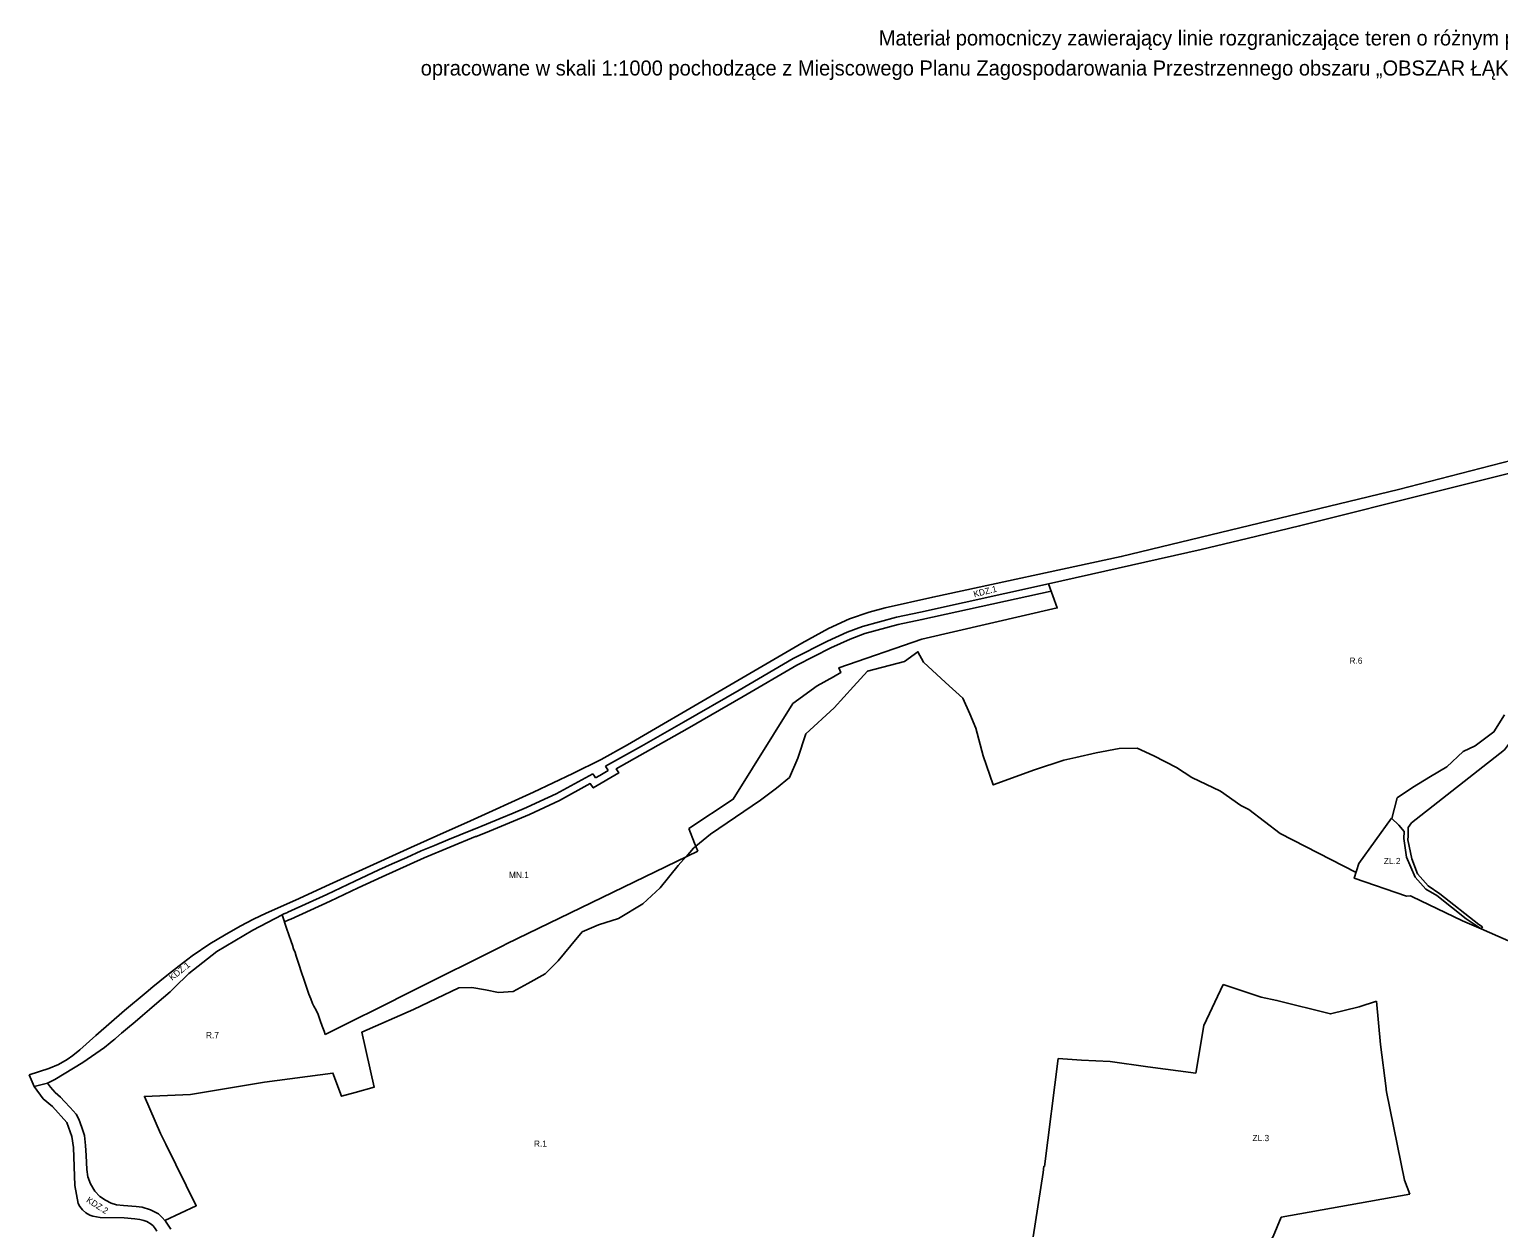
# Model space of a CAD drawing. Extents: x 7418237 to 7420198, y 5543414 to 5545133.
# Drawn here: x 7418237 to 7419412, y 5544174 to 5545133 of the extents above; entities that cross this region are included whole.
import ezdxf

# ---------------------------------------------------------------- set-up
doc = ezdxf.new("R2010")
doc.units = 0
for name, color, linetype in [('info', 7, 'Continuous'), ('linie rozgraniczające', 7, 'Continuous'), ('nieprzekraczalne linie zabudowy', 7, 'Continuous'), ('przeznaczenia terenów', 7, 'Continuous')]:
    doc.layers.add(name, color=color, linetype=linetype)

msp = doc.modelspace()

# ---------------------------------------------------------------- linework, layer by layer
at = {"layer": 'linie rozgraniczające'}
for p, q in [((7418699.9, 5544540.4), (7418697.8, 5544543.7)), ((7418589.7, 5544499.9), (7418562.9, 5544488)), ((7419336, 5544485.9), (7419336.1, 5544491.6)), ((7419362.2, 5544440.2), (7419353.5, 5544445.4)), ((7418449.9, 5544436.7), (7418426.4, 5544426.1)), ((7419338, 5544439.7), (7419341.3, 5544440.1)), ((7419341.3, 5544440.1), (7419342.3, 5544439.6)), ((7419342.3, 5544439.6), (7419382.9, 5544420.2)), ((7419382.9, 5544420.2), (7419397.8, 5544413.7)), ((7418405.6, 5544415.7), (7418393.1, 5544408.7)), ((7418542.9, 5544363.8), (7418615.6, 5544400.2)), ((7418347, 5544376.4), (7418335.9, 5544367.4)), ((7418517, 5544350.8), (7418542.9, 5544363.8)), ((7418542.9, 5544363.8), (7418542.9, 5544363.8)), ((7419191.5, 5544369.2), (7419176, 5544336.3)), ((7419221.8, 5544359.1), (7419191.5, 5544369.2)), ((7418494.3, 5544339.5), (7418517, 5544350.8)), ((7419314, 5544355.9), (7419300.3, 5544351.3)), ((7418473.6, 5544329.1), (7418494.3, 5544339.5)), ((7419176, 5544336.3), (7419169.7, 5544298.3)), ((7419059.6, 5544310.1), (7419048.8, 5544223.6)), ((7419078.3, 5544308.6), (7419059.6, 5544310.1)), ((7419336.5, 5544212.8), (7419322.2, 5544283.4)), ((7418248.3, 5544277.8), (7418255.6, 5544271.6)), ((7418255.6, 5544271.6), (7418267, 5544258.7)), ((7419048.2, 5544223.9), (7419047.5, 5544218.9)), ((7419048.8, 5544223.6), (7419048.2, 5544223.9)), ((7418273.6, 5544208.4), (7418276.2, 5544194.1)), ((7419047.5, 5544218.9), (7419039.6, 5544167.5)), ((7419340.8, 5544201.6), (7419336.5, 5544212.8)), ((7419237.9, 5544183.2), (7419340.8, 5544201.6)), ((7418276.2, 5544194.1), (7418277.6, 5544191.6))]:
    msp.add_line(p, q, dxfattribs=at)
for points in [[(7418875.3, 5544643.7), (7418890.9, 5544650.9), (7418903.3, 5544655.5), (7418930.4, 5544662.8), (7418949.5, 5544666.9), (7419051.8, 5544689.5), (7419173.9, 5544717.1), (7419210.8, 5544725.8), (7419252.6, 5544735.9), (7419477.9, 5544792.5), (7419492.7, 5544796.3), (7419508.2, 5544800.3), (7419538, 5544807.6), (7419572.4, 5544815.5), (7419587.6, 5544818.4), (7419604.4, 5544821.1), (7419625.7, 5544824.5)], [(7419521.6, 5544813.9), (7419331.6, 5544764.9), (7419110, 5544711.3), (7418959.3, 5544678.9), (7418921.3, 5544670.3), (7418908.6, 5544667), (7418892.9, 5544661.5), (7418876.1, 5544653.8), (7418854.6, 5544642.1), (7418787.6, 5544603), (7418715.2, 5544560.8), (7418694.3, 5544549.2), (7418671.5, 5544537.9), (7418640.2, 5544522.9), (7418589.7, 5544499.9)], [(7418764.3, 5544493.9), (7418799.8, 5544517.3), (7418847.4, 5544593.8), (7418866.9, 5544607.9), (7418880, 5544615.3), (7418885.8, 5544618.6), (7418884.3, 5544622.5), (7418950.6, 5544645.3), (7419058.9, 5544670.3), (7419051.8, 5544689.5)], [(7418697.8, 5544543.7), (7418726.5, 5544559.8), (7418760, 5544578.9), (7418804.7, 5544604.6), (7418847.8, 5544629.8), (7418875.3, 5544643.7)], [(7418770, 5544479.7), (7418781.6, 5544489.4), (7418821.7, 5544516.5), (7418834.3, 5544526.2), (7418844.8, 5544534.6), (7418851.4, 5544550.1), (7418858, 5544569.7), (7418880.4, 5544590.3), (7418895.9, 5544607.5), (7418907.1, 5544619.8), (7418936.7, 5544627.4), (7418947.5, 5544635.2), (7418952, 5544627), (7418969.6, 5544610.7), (7418983.3, 5544598.2), (7418988.9, 5544585.5), (7418993.9, 5544574.2), (7418999.7, 5544552), (7419007.7, 5544528.8), (7419040.8, 5544540.9), (7419064.1, 5544548.6), (7419073.7, 5544550.7), (7419090, 5544554.3), (7419108.5, 5544558), (7419122.7, 5544558.2), (7419136.2, 5544551.9), (7419154.2, 5544542.8), (7419166.6, 5544534.7), (7419189.3, 5544523.8), (7419205.7, 5544512.2), (7419212.1, 5544509.2), (7419237.1, 5544489.8), (7419297.8, 5544458.8)], [(7419326.3, 5544502), (7419330.7, 5544518.3), (7419342.9, 5544526.7), (7419357.4, 5544535.5), (7419370.3, 5544543.1), (7419383.4, 5544555.4), (7419393, 5544559.9), (7419408, 5544571.1), (7419416.3, 5544584.7)], [(7419425.9, 5544569.5), (7419416.3, 5544556.9), (7419342.2, 5544498.4), (7419339.3, 5544494.6), (7419339.3, 5544487.9)], [(7418658.2, 5544521.7), (7418687.5, 5544537.7)], [(7418687.5, 5544537.7), (7418688.8, 5544535.8), (7418689.7, 5544534.4)], [(7418689.7, 5544534.4), (7418693.1, 5544536.4), (7418699.9, 5544540.4)], [(7418613.6, 5544502), (7418623.8, 5544506.2), (7418634.5, 5544510.7), (7418645.4, 5544515.8), (7418658.2, 5544521.7)], [(7418592.3, 5544493.2), (7418602.6, 5544497.5), (7418613.6, 5544502)], [(7419336.1, 5544491.6), (7419332, 5544496.5), (7419326.2, 5544502.1), (7419300, 5544465.9)], [(7418497.4, 5544451.8), (7418507, 5544456.3), (7418516.6, 5544460.8), (7418521.9, 5544463.2), (7418527.3, 5544465.6), (7418538.8, 5544470.8), (7418550.3, 5544476), (7418561.1, 5544480.4), (7418571.8, 5544484.8), (7418591.5, 5544492.9), (7418591.9, 5544493), (7418592.1, 5544493.1), (7418592.3, 5544493.2)], [(7418764.3, 5544493.9), (7418768.9, 5544482.2), (7418771.5, 5544475.9)], [(7418562.9, 5544488), (7418542.1, 5544478.6), (7418500.6, 5544459.8), (7418477.2, 5544449), (7418449.9, 5544436.7)], [(7419353.5, 5544445.4), (7419344.9, 5544455), (7419338.1, 5544471), (7419336, 5544485.9)], [(7419339.3, 5544487.9), (7419339.2, 5544484.9), (7419342.4, 5544469.6), (7419346.9, 5544457.7), (7419355.3, 5544448.1), (7419364.8, 5544441.6), (7419395.8, 5544417.2), (7419398.8, 5544415.3)], [(7418345.4, 5544180.5), (7418370.5, 5544192.2), (7418346.3, 5544241.5), (7418342.1, 5544250), (7418329.1, 5544279.7), (7418365.9, 5544281.2), (7418425.1, 5544291), (7418479.8, 5544298.3), (7418486.8, 5544279.8), (7418497.7, 5544282.9), (7418512.8, 5544287.1), (7418503, 5544331.1), (7418544.2, 5544349.2), (7418562.6, 5544358.1), (7418580.5, 5544366.5), (7418590.9, 5544366.7), (7418601.9, 5544364.8), (7418612.3, 5544362.8), (7418623.9, 5544363.6), (7418635.7, 5544369.9), (7418649.6, 5544377.8), (7418659.8, 5544388), (7418670.1, 5544400.4), (7418679.2, 5544411.2), (7418692, 5544416.9), (7418708.1, 5544422), (7418727.7, 5544433.6), (7418741.3, 5544446.4), (7418755.9, 5544464.3), (7418762.2, 5544471.4)], [(7418615.6, 5544400.2), (7418618.6, 5544401.7), (7418771.5, 5544475.9)], [(7419300, 5544465.9), (7419296.3, 5544454.1), (7419338, 5544439.7)], [(7418439.2, 5544424.9), (7418440.7, 5544425.6), (7418442.2, 5544426.2), (7418442.9, 5544426.6), (7418443.7, 5544426.9), (7418475, 5544441.1), (7418486.2, 5544446.5), (7418497.4, 5544451.8)], [(7419397.8, 5544413.7), (7419385.8, 5544421.6), (7419362.2, 5544440.2)], [(7418439.2, 5544424.9), (7418427.4, 5544418.8), (7418415.7, 5544412.6), (7418401.3, 5544404.1), (7418387, 5544395.6)], [(7418426.4, 5544426.1), (7418416.4, 5544421.3), (7418405.6, 5544415.7)], [(7418473.6, 5544329.1), (7418472.7, 5544331.8), (7418471.3, 5544335.9), (7418469.7, 5544340.5), (7418468.1, 5544345.2), (7418466.4, 5544348.6), (7418464.6, 5544351.9), (7418464.1, 5544352.9), (7418463.6, 5544353.9), (7418462.1, 5544357.6), (7418460.6, 5544361.4), (7418459.5, 5544364.6), (7418458.3, 5544367.8), (7418456.5, 5544373.3), (7418454.7, 5544378.8), (7418452.6, 5544385.3), (7418450.5, 5544391.8), (7418449.5, 5544394.7), (7418448.4, 5544397.6), (7418447.4, 5544400.6), (7418446.4, 5544403.6), (7418442.8, 5544414.2), (7418439.2, 5544424.9)], [(7418393.1, 5544408.7), (7418381.4, 5544401.6), (7418367.2, 5544392)], [(7419398.8, 5544415.3), (7419397.8, 5544413.7), (7419428.8, 5544400.2)], [(7418304.6, 5544324.8), (7418305.4, 5544325.5), (7418306.2, 5544326.2), (7418310.9, 5544330.2), (7418315.6, 5544334.2), (7418321.6, 5544339.3), (7418327.5, 5544344.4), (7418333.3, 5544349.3), (7418339, 5544354.2), (7418344.4, 5544358.7), (7418349.7, 5544363.3), (7418351.3, 5544364.9), (7418352.8, 5544366.5), (7418364.6, 5544377.9), (7418375.8, 5544386.8), (7418387, 5544395.6)], [(7418367.2, 5544392), (7418356.8, 5544384.2), (7418347, 5544376.4)], [(7418335.9, 5544367.4), (7418330.4, 5544362.9), (7418313.3, 5544348.3), (7418290.4, 5544328.3), (7418277.4, 5544316.8), (7418271.9, 5544312.3), (7418267.4, 5544309.1), (7418260.5, 5544305.3), (7418252.7, 5544302.1), (7418237.1, 5544297)], [(7419300.3, 5544351.3), (7419277.2, 5544345.7), (7419234.5, 5544356.4), (7419221.8, 5544359.1)], [(7419321.8, 5544286), (7419317.2, 5544321.1), (7419314, 5544355.9)], [(7418297.2, 5544318.9), (7418279.9, 5544306.7), (7418257.4, 5544293.2), (7418251.6, 5544290.2), (7418241.1, 5544287.7)], [(7418304.6, 5544324.8), (7418301.7, 5544322.5), (7418297.2, 5544318.9)], [(7419169.7, 5544298.3), (7419131.4, 5544303.4), (7419101.3, 5544307.5), (7419078.3, 5544308.6)], [(7418237.1, 5544297), (7418241.1, 5544287.5), (7418248.3, 5544277.8)], [(7418251.6, 5544290.2), (7418253.9, 5544287.1), (7418257.8, 5544282.8), (7418262.1, 5544279.2), (7418265.3, 5544275.7), (7418269.7, 5544270.7), (7418274.5, 5544265.4), (7418276.7, 5544261.4), (7418279.1, 5544254.9), (7418281.1, 5544248.5), (7418282.1, 5544240.5), (7418282.6, 5544232.5), (7418283, 5544221.2), (7418283.9, 5544215.3), (7418285.9, 5544209.7), (7418289.4, 5544204), (7418293.5, 5544199.7), (7418297.9, 5544196.6), (7418302.6, 5544194.4), (7418306.8, 5544193.1), (7418312.4, 5544192.5), (7418322.5, 5544191.7), (7418327.2, 5544191), (7418333.9, 5544189.1), (7418340.4, 5544185.7)], [(7419322.2, 5544283.4), (7419321.9, 5544285.1), (7419321.8, 5544286)], [(7418267, 5544258.7), (7418271.2, 5544247.5), (7418272.3, 5544238.7), (7418273.6, 5544208.4)], [(7418277.6, 5544191.6), (7418279.6, 5544189), (7418282.2, 5544186.6), (7418285.6, 5544184.8), (7418287.8, 5544184), (7418293.7, 5544182.9), (7418313, 5544182.5), (7418321.4, 5544181.7), (7418325.4, 5544181.2), (7418328.6, 5544180.4), (7418331, 5544179.6), (7418334.5, 5544177.6), (7418336, 5544176.1), (7418337.8, 5544174.1), (7418339.1, 5544172)], [(7418350.1, 5544173.4), (7418346, 5544179.8), (7418343.1, 5544183.2), (7418340.4, 5544185.7)], [(7419215.7, 5544151.9), (7419222.8, 5544153.8), (7419231.5, 5544167.6), (7419237.9, 5544183.2)]]:
    msp.add_lwpolyline(points, dxfattribs=at)
at = {"layer": 'nieprzekraczalne linie zabudowy'}
for points in [[(7419053.9, 5544683.8), (7418950.7, 5544661), (7418931.8, 5544657), (7418905.1, 5544649.8), (7418893.2, 5544645.4), (7418877.9, 5544638.3), (7418850.7, 5544624.6), (7418807.7, 5544599.4), (7418762.9, 5544573.7), (7418729.5, 5544554.6), (7418706.3, 5544541.6), (7418708.3, 5544538.4), (7418687.9, 5544526.4), (7418685.5, 5544529.8), (7418660.9, 5544516.4), (7418636.9, 5544505.2), (7418604.9, 5544491.9), (7418595, 5544487.8), (7418594.5, 5544487.6), (7418594, 5544487.4), (7418593.9, 5544487.4), (7418552.7, 5544470.5), (7418519.1, 5544455.3), (7418500, 5544446.4), (7418477.5, 5544435.7), (7418446.2, 5544421.5), (7418444.6, 5544420.8), (7418441.1, 5544419.2)], [(7418762.1, 5544471.3), (7418768.2, 5544478.2), (7418770, 5544479.7)]]:
    msp.add_lwpolyline(points, dxfattribs=at)

# ---------------------------------------------------------------- texts
at = {"layer": 'info'}
for s, p in [('Materiał pomocniczy zawierający linie rozgraniczające teren o różnym przeznaczeniu i różnych warunkach zagospodarowania terenu, ', (7418916.2, 5545120)), ('opracowane w skali 1:1000 pochodzące z Miejscowego Planu Zagospodarowania Przestrzennego obszaru „OBSZAR ŁĄKOWY-REJON ULICY TYNIECKIEJ” zatwierdzonego uchwałą RMK Nr CIX/2889/18 z dnia 12 września 2018 r.', (7418550, 5545096))]:
    msp.add_text(s, height=12, dxfattribs=at).set_placement(p)
at = {"layer": 'przeznaczenia terenów'}
for s, rotation, p in [('KDZ.1', 14.1355, (7418992.6, 5544678.7)), ('KDZ.1', 38.6416, (7418351.3, 5544372)), ('KDZ.2', 327.2942, (7418282.2, 5544195.6))]:
    msp.add_text(s, height=5, rotation=rotation, dxfattribs=at).set_placement(p)
for s, p in [('R.6', (7419292.5, 5544625.6)), ('ZL.2', (7419319.9, 5544465.4)), ('MN.1', (7418620.5, 5544454.3)), ('R.7', (7418378.3, 5544326.2)), ('R.1', (7418640.5, 5544239.4)), ('ZL.3', (7419214.9, 5544243.9))]:
    msp.add_text(s, height=5, dxfattribs=at).set_placement(p)

doc.saveas('drawing.dxf')
